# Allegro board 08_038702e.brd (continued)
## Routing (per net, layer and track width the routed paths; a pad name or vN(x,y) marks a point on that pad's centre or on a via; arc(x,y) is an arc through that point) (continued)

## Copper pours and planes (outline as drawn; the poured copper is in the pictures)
0.95V on TOP: 10.72,7.47 10.72,3.28 8.31,3.28 8.31,5.95 8.18,6.08 7.55,6.08 7.55,7.47
0.95V on BOTTOM: 10.34,7.47 10.34,2.01 7.55,2.01 7.55,7.47
0.95V on L9_POWER: 27.61,36.81 29.14,34.53 51.49,34.53 52.88,33.13 52.88,26.14 53.01,26.14 55.93,23.22 62.03,23.22 64.95,20.3 64.95,17.63 63.68,16.36 61.52,16.36 61.14,15.98 59.74,15.98 58.73,14.97 58.09,14.97 55.3,12.17 52.25,12.17 51.87,11.79 49.96,11.79 48.44,10.27 30.91,10.27 28.63,7.98 28.63,6.84 28.37,6.59 21.01,6.59 16.56,2.14 15.8,2.14 14.4,0.74 8.94,0.74 7.04,2.65 7.04,4.93 3.74,8.24 2.97,8.24 0.56,10.65 0.56,41 1.45,41.89 5.51,41.89 6.4,41 6.4,38.84 5.13,37.57 5.13,37.07 5.64,36.56 5.64,33.13 6.78,31.99 15.17,31.99 20.12,36.94 24.31,37.32 27.23,37.07 27.48,36.94 ; 1 cut-out
0.95V on L12_POWER: 6.53,0.62 6.28,1.25 6.28,5.06 4.5,6.84 1.58,6.84 0.56,7.86 0.56,51.8 1.96,53.19 6.53,53.19 8.31,51.42 8.31,34.78 5.77,32.24 5.77,18.65 6.66,17.76 16.56,17.76 18.98,15.35 31.42,15.35 34.34,12.43 37.39,12.43 41.2,8.62 53.01,8.62 53.77,9.38 53.77,11.28 52.88,12.17 51.23,12.17 50.98,12.43 50.98,13.44 51.23,13.7 56.82,13.7 57.58,14.46 57.58,16.49 61.27,20.17 63.68,20.17 63.74,20.11 81.65,20.11 83.87,17.89 83.87,1.76 82.73,0.62 16.56,0.62 15.93,1.25 15.17,1.25 14.53,0.62 ; 7 cut-outs
1.0V on TOP: 52,12.05 54.03,12.05 54.92,12.94 56.82,12.94 57.58,13.57 58.6,13.57 59.11,12.81 59.49,13.32 59.11,13.95 59.11,14.33 58.85,14.59 52.76,14.59 52,13.82
1.8V on TOP: 64.57,3.28 64.57,1.63 59.23,1.63 59.23,3.41 59.62,3.79 60.12,3.79 60.38,4.05 60.38,6.08 60.89,6.08 60.89,3.66 61.27,3.28
1.8V on L10_POWER: 58.47,12.68 58.47,2.78 58.98,2.27 62.41,2.27 65.08,4.93 67.49,4.93 68.38,4.05 68.38,1.63 68.76,1.25 78.03,1.25 80.44,3.66 80.44,6.46 78.54,8.36 75.87,8.36 75.62,8.11 75.62,6.84 75.36,6.59 72.06,6.59 70.92,7.73 70.92,10.4 69.65,11.67 66.35,11.67 63.93,14.08 59.87,14.08 ; 2 cut-outs
1.8V on L11_POWER: 13.64,13.95 15.8,13.95 15.8,5.44 16.05,5.19 19.74,5.19 23.17,8.62 67.24,8.62 67.24,9.51 71.17,9.51 71.81,10.14 71.81,12.43 72.95,13.57 83.24,13.57 84.13,12.68 84.13,1.63 83.11,0.62 18.34,0.62 13.64,5.32 ; 7 cut-outs
1.35V on TOP: 59.74,13.82 62.54,13.82 62.92,14.21 64.31,14.21 64.31,14.97 63.68,15.6 59.62,15.6 59.49,15.48 59.49,14.08
1.35V on L18_SIG: 30.15,1.63 30.15,3.41 50.22,3.41 51.11,4.3 51.11,10.52 52.88,12.3 52.88,14.84 53.14,15.09 59.74,15.09 59.87,14.97 62.16,14.97 62.54,14.59 62.54,13.95 62.28,13.7 61.39,13.7 60.76,13.06 60.76,1.89 59.87,1 34.34,1 33.83,1.51 32.06,1.51 31.55,1 30.79,1
3.3V on L11_POWER: 81.46,60.18 81.46,52.56 73.84,52.56 73.84,57 56.8,56.89 56.89,56.96 56.86,57.07 56.83,57.1 56.76,57.13 56.68,57.11 56.54,57.04 56.38,57.05 56.28,57.03 56.25,56.93 56.25,56.89 55.04,56.88 54.15,57.77 53.65,57.77 52.88,57 39.3,57 39.3,53.19 34.47,53.19 34.47,57 28.75,57 28.75,59.04 9.96,59.04 9.96,56.62 7.29,53.96 7.29,43.54 2.85,39.1 2.85,38.59 2.08,37.83 1.2,37.83 0.94,38.08 0.94,39.61 1.83,40.49 1.83,41.51 4.75,44.43 4.75,60.18 5.89,61.32 80.44,61.32 ; 2 cut-outs
GND on TOP: outline of 175 points within 57.84,33.14 97.22,55.47
GND on TOP: outline of 116 points within 59.74,7.11 97.48,24.99 ; 1 cut-out
GND on TOP: 96.57,7.35 96.57,11.92 91.75,11.92 91.75,15.6 96.57,15.6 96.57,20.81 92,20.81 92,24.62 96.57,24.62 96.57,33.51 91.87,33.51 91.87,37.32 96.57,37.32 96.57,42.4 92,42.4 92,46.21 96.57,46.21 96.57,51.16 91.75,51.16 91.75,55.23 99.62,55.23 99.62,7.35
GND on TOP: 78.03,23.86 76.77,24.38 76.25,25.64 76.25,26.4 76.77,27.65 78.03,28.18 78.88,28.18 79.46,28.39 80.08,28.47 80.82,28.47 81.55,28.85 82.36,28.98 93.21,28.98 93.77,29.31 94.4,29.43 95.45,29.43 96.7,28.91 97.22,27.65 97.22,26.66 96.7,25.41 95.45,24.89 94.4,24.89 93.98,24.94 93.58,25.09 82.82,25.09 82.01,24.71 81.14,24.58 81.11,24.58 80.48,24.05 79.68,23.86
GND on TOP: 15.04,3.28 15.04,0.62 17.71,0.62 18.21,1.12 18.21,2.9 19.61,4.3 21.77,4.3 21.77,4.81 21.26,4.81 21.26,7.22 20.12,7.22 18.85,5.95 18.85,5.19 17.71,4.05 15.67,4.05 15.17,3.41
GND on BOTTOM: 11.61,0.36 11.61,6.84 13.01,6.84 13.01,4.81 14.78,4.81 14.78,2.01 18.34,2.01 18.34,0.36
GND on BOTTOM: 22.53,7.22 22.53,5.19 24.31,5.19 24.31,7.22
GND on BOTTOM: 60.38,34.53 60.38,24.62 70.16,24.62 70.16,34.53 ; 1 cut-out
GND on L2_GND: 3.74,0.62 2.34,1 1.2,2.01 0.69,3.16 0.69,58.27 0.94,59.54 1.58,60.43 2.59,61.2 3.74,61.32 96.7,61.32 97.59,61.2 98.6,60.43 99.11,59.67 99.37,58.66 99.37,3.41 99.11,2.39 98.6,1.51 97.59,0.87 96.45,0.62 ; 12 cut-outs
GND on L3_SIG: 99.37,54.85 99.37,7.6 86.29,7.6 82.22,11.67 66.47,11.67 66.47,14.59 65.2,15.73 63.3,15.73 62.16,16.87 62.16,17.51 61.01,17.89 61.01,21.44 65.58,21.44 65.58,19.29 66.6,18.27 69.01,18.27 70.41,19.67 73.84,19.67 76.76,22.59 76.76,40.88 76.13,41.51 73.33,41.51 72.06,40.24 72.06,38.72 70.66,38.72 68.76,40.62 59.36,40.62 59.36,42.02 62.16,43.42 66.35,47.61 75.49,47.61 77.78,49.89 77.78,52.43 80.19,54.85 ; 1 cut-out
GND on L5_GND: 3.74,0.62 2.21,1 1.07,2.14 0.69,3.28 0.69,58.91 1.32,60.31 2.34,61.2 3.74,61.32 96.57,61.32 97.59,61.2 98.6,60.43 99.11,59.67 99.37,58.53 99.37,3.41 99.11,2.39 98.6,1.51 97.59,0.87 96.45,0.62 ; 6 cut-outs
GND on L8_GND: 3.74,0.62 2.21,1 1.07,2.14 0.69,3.28 0.69,58.91 1.32,60.31 2.34,61.2 3.74,61.32 96.57,61.32 97.59,61.2 98.6,60.43 99.11,59.67 99.37,58.53 99.37,3.41 99.11,2.39 98.6,1.51 97.59,0.87 96.45,0.62 ; 6 cut-outs
GND on L13_GND: 3.74,0.62 2.21,1 1.07,2.14 0.69,3.28 0.69,58.91 1.32,60.31 2.34,61.2 3.74,61.32 96.57,61.32 97.59,61.2 98.6,60.43 99.11,59.67 99.37,58.53 99.37,3.41 99.11,2.39 98.6,1.51 97.59,0.87 96.45,0.62 ; 6 cut-outs
GND on L16_GND: 3.74,0.62 2.21,1 1.07,2.14 0.69,3.28 0.69,58.91 1.32,60.31 2.34,61.2 3.74,61.32 96.57,61.32 97.59,61.2 98.6,60.43 99.11,59.67 99.37,58.53 99.37,3.41 99.11,2.39 98.6,1.51 97.59,0.87 96.45,0.62 ; 6 cut-outs
GND on L19_GND: 3.74,0.62 2.21,1 1.07,2.14 0.69,3.28 0.69,58.91 1.32,60.31 2.34,61.2 3.74,61.32 96.57,61.32 97.59,61.2 98.6,60.43 99.11,59.67 99.37,58.53 99.37,3.41 99.11,2.39 98.6,1.51 97.59,0.87 96.45,0.62 ; 8 cut-outs
VCC-1P35 on BOTTOM: 47.55,61.58 47.55,60.18 48.57,60.18 48.57,61.58
VCC-1P35 on L12_POWER: 48.95,14.59 56.82,14.59 56.82,16.62 59.23,19.03 59.23,58.02 55.81,61.45 47.55,61.45 45.39,59.29 38.66,59.29 38.15,58.78 38.15,57.77 38.66,57.26 42.09,57.26 44.63,54.72 48.19,54.72 48.95,53.96 ; 1 cut-out
VCC-3P3V on BOTTOM: 42.98,59.93 42.98,61.45 44.88,61.45 45.39,60.69 46.15,60.69 46.15,60.18 45.14,60.18 44.88,59.93
VCC-3P3V on L3_SIG: 10.34,54.21 10.34,59.93 10.85,60.43 22.91,60.43 22.91,58.53 15.04,58.53 15.04,54.21
VCC-3P3V on L6_SIG: 21.39,58.66 21.39,61.45 46.03,61.45 46.03,59.8 23.42,59.8 23.42,58.66
VCC-3P3V-IO on L11_POWER: 5.01,31.1 26.6,31.1 26.6,37.83 31.93,37.83 31.93,27.41 30.91,26.4 16.18,26.4 15.8,26.02 11.74,26.02 11.61,25.89 11.61,11.16 7.61,7.16 5.2,7.16 5.13,7.22 2.97,7.22 2.34,7.86 2.34,11.41 6.02,11.41 6.78,12.17 6.78,13.19 6.4,13.57 4.5,13.57 3.1,14.97 3.1,17.63 5.01,19.54
VCC-3P3V-IO on L12_POWER: 38.28,12.17 38.28,12.94 34.72,12.94 28.25,19.41 28.25,24.87 26.34,26.78 26.34,32.87 27.87,34.4 27.87,37.19 33.58,37.19 33.58,41.64 33.33,41.89 11.86,41.89 11.23,42.53 11.23,54.85 26.47,54.85 26.47,59.67 31.93,59.67 31.93,54.85 33.71,54.85 33.71,50.65 46.03,50.65 46.03,47.73 31.42,47.73 31.42,52.69 14.78,52.69 13.26,51.16 13.26,49.13 14.59,47.8 19.17,47.8 23.55,43.42 35.74,43.42 35.74,34.27 29.52,28.05 29.52,26.14 30.15,25.51 30.15,20.81 35.61,15.35 38.53,15.35 39.68,14.21 40.44,14.21 42.6,12.05 42.6,9.13 41.33,9.13 ; 1 cut-out
VCCO-DDR on TOP: 48.95,2.9 48.95,6.59 53.39,6.59 53.39,5.19 50.09,5.19 50.09,2.9
VCCO-DDR on BOTTOM: 48.69,4.93 48.69,2.27 49.71,2.27 49.71,4.93
VCCO-DDR on L10_POWER: 52.25,15.73 50.09,15.73 48.44,14.08 48.44,5.95 49.2,5.19 49.2,3.54 49.46,3.28 52.76,3.28 53.01,3.54 53.01,5.06 51.11,6.97 51.11,12.55 52.63,14.08 52.63,15.35
VCCO-DDR on L11_POWER: 25.07,14.46 22.53,14.46 18.34,18.65 18.34,24.62 40.69,24.62 40.69,18.27 45.39,13.57 50.22,13.57 50.22,16.36 52.76,16.36 52.76,10.27 29.26,10.27
VCCO_1P8V on L12_POWER: 38.03,26.52 38.03,42.91 37.01,43.92 26.98,43.92 25.83,45.07 22.4,45.07 19.1,48.37 14.66,48.37 13.64,49.38 13.64,50.02 14.78,51.16 20.75,51.16 22.91,49 27.36,49 29.52,46.84 47.04,46.84 48.31,45.57 48.31,34.4 48.44,34.4 48.44,26.52
VCCO_12 on TOP: 14.15,37.57 14.15,36.43 15.17,36.43 15.17,37.57
VCCO_12 on L9_POWER: 18.85,15.73 18.85,30.72 21.13,30.72 21.13,34.02 23.29,34.4 23.93,34.78 24.44,34.78 26.34,34.02 26.34,32.37 24.94,30.97 24.94,28.94 26.47,27.41 26.47,26.4 23.55,23.48 23.55,17.13 26.72,17.13 26.72,16.11 26.34,15.73
VCCO_12 on L11_POWER: 13.26,32.87 13.26,37.83 17.83,37.83 17.83,36.3 25.45,36.3 25.71,36.05 25.71,31.73 25.45,31.48 18.21,31.48 16.82,32.87
VCCO_13 on TOP: 17.2,38.34 17.2,36.94 18.34,36.94 19.1,36.18 19.1,31.73 18.34,30.97 18.34,17 19.36,15.98 21.39,15.98 21.77,16.36 21.77,16.62 21.52,16.87 19.48,16.87 19.1,17.25 19.1,24.75 20.12,25.76 20.12,26.27 19.1,27.29 19.1,30.21 20.12,31.22 20.12,35.8 19.99,35.92 19.99,36.94 18.59,38.34
VCCO_13 on L12_POWER: 18.09,16.62 18.09,18.27 6.91,18.27 6.21,18.97 6.21,22.65 12.75,29.19 12.75,37.19 13.39,37.83 15.42,37.83 15.67,37.57 15.67,36.56 16.82,35.41 21.01,35.41 22.02,34.4 22.02,25.38 27.1,25.38 27.61,24.87 27.61,17 26.47,15.86 18.85,15.86
VCCO_33_34 on TOP: 19.61,41.89 19.61,40.49 17.07,40.49 17.07,41.89
VCCO_33_34 on L11_POWER: 40.95,18.65 40.95,29.83 38.41,29.83 38.15,30.08 38.15,31.99 32.56,31.99 32.56,38.34 18.98,38.34 17.32,39.99 17.32,42.27 15.04,44.56 15.04,46.72 46.92,46.72 47.42,46.21 47.42,44.81 48.19,44.05 48.19,35.67 52.12,31.73 56.82,31.73 56.82,28.05 49.84,28.05 49.84,23.73 47.68,21.57 44.76,21.57 44.25,21.06 44.25,19.92 45.01,19.16 49.2,19.16 49.84,18.52 49.84,14.08 45.52,14.08
VCCPCOM-1P8V on L10_POWER: 6.66,1.76 6.66,13.82 1.07,13.82 1.07,29.95 15.17,29.95 15.24,37.51 15.29,37.56 15.33,37.59 15.36,37.64 15.33,37.68 15.32,37.69 15.28,37.7 15.24,37.7 15.17,42.53 15.29,42.65 15.29,43.03 15.17,43.29 11.99,46.46 5.39,46.46 5.39,51.92 10.59,51.92 14.66,55.99 14.66,60.18 48.31,60.18 49.46,61.32 53.14,61.32 54.28,60.18 67.36,60.18 69.52,58.02 69.52,50.15 65.46,46.08 61.39,46.08 60.38,47.1 60.38,49.77 58.6,51.54 32.06,51.54 30.91,50.4 30.91,46.34 33.07,44.18 33.07,37.19 36.88,37.19 36.88,32.87 33.07,32.87 33.07,27.41 50.09,27.41 51.87,25.64 51.87,24.87 48.06,21.06 48.06,15.6 47.93,15.6 47.93,5.82 48.82,4.93 48.82,2.9 47.93,2.01 40.69,2.01 40.69,15.6 31.17,15.6 31.17,18.4 22.91,18.4 22.91,13.82 15.42,13.82 14.53,12.94 14.53,10.65 15.93,9.25 15.93,1.76 ; 5 cut-outs
VCCPINT on L2_GND: 51.11,11.16 51.11,10.01 51.87,9.25 53.39,9.25 53.39,11.16
VCCPINT on L10_POWER: 51.74,10.4 53.01,10.4 53.52,9.89 53.52,9.51 54.03,9 54.03,8.11 57.84,4.3 57.84,2.01 58.09,1.76 62.79,1.76 65.58,4.55 67.24,4.55 67.74,4.05 67.74,1.63 66.73,0.62 56.69,0.62 55.68,1.63 55.68,4.05 53.27,6.46 53.27,8.49 52.88,8.87 51.87,8.87 51.49,9.25 51.49,10.14
VCCPINT on L12_POWER: 45.9,9.13 44.76,10.27 44.25,10.27 43.87,10.65 43.87,12.43 41.33,14.97 39.55,14.97 38.79,15.73 36.25,15.73 34.72,17.25 34.72,24.49 30.53,24.49 30.53,25.76 29.9,26.4 29.9,26.91 30.53,27.54 37.52,27.54 37.52,26.4 37.77,26.14 37.77,20.17 40.69,17.25 48.44,17.25 48.44,14.21 48.82,13.82 48.82,11.67 52.5,11.67 53.39,10.78 53.39,9.76 52.76,9.13
VDD_INTERFACE on L10_POWER: 61.9,18.65 64.44,16.11 70.28,16.11 72.32,14.08 75.11,14.08 75.11,6.97 73.71,6.97 72.19,8.49 72.19,10.78 70.92,12.05 69.78,12.05 68.38,13.44 65.08,13.44 63.93,14.59 61.52,14.59 60,16.11 60,22.21 58.98,23.22 58.09,23.22 56.44,24.87 56.44,32.49 59.87,32.49 60.89,31.48 60.89,30.72 59.62,29.45 59.62,25.76 60,25.38 61.77,25.38 62.28,24.87 62.28,23.6 61.9,23.22 ; 2 cut-outs
VDDA_GPO_PWR on L10_POWER: 86.54,46.46 86.54,57.26 80.7,57.26 80.7,60.18 88.32,60.18 88.32,46.46
VIN on TOP: 16.94,42.78 16.94,44.43 17.58,44.43 17.58,44.69 18.34,44.69 18.34,45.96 19.61,45.96 19.61,42.78
VIN on TOP: 19.1,0.62 18.98,0.74 18.98,3.41 21.13,3.41 21.77,2.78 23.17,2.78 23.17,3.66 23.04,3.92 23.04,4.68 23.17,4.81 24.31,4.81 24.56,5.06 24.56,5.32 25.33,5.32 25.45,5.19 25.45,2.78 25.96,2.39 25.96,0.62
VIN on L9_POWER: 29.52,8.24 31.04,9.76 48.69,9.76 50.09,11.16 52.76,11.16 53.52,11.92 55.81,11.92 58.6,14.71 58.98,14.71 59.87,15.6 61.27,15.6 61.65,15.98 63.93,15.98 67.74,19.79 70.92,19.79 74.73,23.6 74.73,43.67 73.46,44.94 52.25,44.94 51.49,45.7 20.12,45.7 19.61,45.19 19.61,43.42 18.09,41.89 16.82,41.89 16.05,42.65 16.05,47.99 25.71,57.64 43.36,57.64 44.5,56.5 48.19,56.5 49.33,57.64 58.85,57.64 59.49,57 59.49,48.5 59.74,48.24 77.14,48.24 79.3,46.08 79.3,13.7 77.4,11.79 68.38,11.79 64.7,8.11 64.7,1.63 29.14,1.63 27.99,0.62 18.21,0.62 18.09,0.74 18.09,2.9 21.01,5.82 21.39,5.82 21.52,5.7 21.52,5.19 21.64,5.06 23.93,5.06 24.06,5.19 24.06,5.7 24.18,5.82 27.1,5.82 27.48,6.2 28.5,6.2 29.52,7.22 ; 4 cut-outs
1P3_SUPPLY_A on L11_POWER: 63.68,9 63.68,19.54 66.47,19.54 69.78,22.84 69.78,23.35 69.01,24.11 69.01,25.51 70.16,26.65 70.16,27.29 70.41,27.54 74.35,27.54 74.86,28.05 74.86,29.7 74.47,30.08 70.66,30.08 70.16,30.59 70.16,31.35 70.54,31.73 74.09,31.73 74.86,32.49 74.86,33.64 74.09,34.4 70.92,34.4 70.54,34.78 70.54,36.81 74.73,36.81 78.03,33.51 78.03,21.95 70.92,14.84 70.92,11.92 71.17,11.92 71.17,10.52 71.05,10.4 66.73,10.4 66.6,10.27 66.6,9 ; 2 cut-outs
1P3_SUPPLY_B on BOTTOM: 66.47,40.37 66.47,39.73 65.58,38.84 64.82,38.84 64.7,38.72 64.7,37.57 64.82,37.45 65.58,37.45 65.84,37.7 68.63,37.7 68.89,37.95 68.89,38.72 68.51,39.1 68.51,39.99 67.87,40.62 66.73,40.62
1P3_SUPPLY_B on L10_POWER: 75.62,8.74 75.62,14.84 72.44,14.84 72.44,14.97 70.92,16.49 64.82,16.49 62.28,19.03 62.28,22.08 68.89,22.08 70.66,23.86 70.66,25.89 70.92,26.14 74.86,26.14 75.36,26.65 75.36,29.45 74.73,30.08 72.95,30.08 72.7,30.33 72.7,34.91 70.28,37.32 64.7,37.32 64.31,36.94 64.31,34.53 64.06,34.27 61.39,34.27 59.62,36.05 59.62,43.42 60.12,43.92 70.92,43.92 74.35,40.49 74.35,36.3 76.76,33.89 80.19,33.89 80.19,14.84 79.68,14.84 79.68,10.14 77.4,10.14 77.4,8.74 ; 1 cut-out
1P3_SUPPLY_B on L19_GND: 64.7,38.72 64.7,37.45 66.22,37.45 66.22,38.72
JX_MGTAVCC on TOP: 8.18,37.45 8.18,34.14 5.89,34.14 5.89,36.18 7.16,37.45
JX_MGTAVCC on L11_POWER: 4.24,13.19 5.89,13.19 6.15,12.94 6.15,12.3 5.77,11.92 1.2,11.92 0.81,12.3 0.81,33 3.74,35.92 6.91,35.92 7.29,35.54 7.29,34.91 2.59,30.21 2.59,14.84
JX_MGTAVTT on TOP: 10.85,37.7 10.85,35.29 11.86,35.29 11.86,37.7
JX_MGTAVTT on L4_SIG: 10.59,37.7 10.59,36.3 10.85,36.05 11.23,36.05 11.36,36.18 11.36,37.45 10.97,37.83 10.72,37.83
JX_VCCO_12 on TOP: 12.63,37.57 12.63,34.53 13.77,34.53 13.77,37.57
JX_VCCO_12 on L9_POWER: 16.82,60.31 63.17,60.31 64.82,58.66 64.7,50.4 63.17,48.88 60.63,48.88 60,49.51 60,58.15 49.2,58.15 48.19,57.13 44.63,57.13 43.61,58.15 25.33,58.15 13.77,46.59 13.77,37.83 14.66,36.94 14.66,34.91 14.4,34.65 12.75,34.65 11.23,36.18 11.23,54.72
JX_VCCO_13 on TOP: 15.8,38.34 15.8,35.16 16.94,35.16 16.94,38.34
JX_VCCO_33_34 on TOP: 14.66,39.35 14.66,40.11 16.05,40.11 16.05,41.26 16.82,41.26 16.82,39.35
JX_VCCO_33_34 on L14_SIG: 14.91,40.37 14.91,39.35 16.94,39.35 16.94,40.37
JX_VCCO_33_34 on L14_SIG: 11.36,0.49 11.23,0.62 11.23,13.95 4.24,13.95 1.07,17.13 1.07,35.41 2.47,36.81 14.91,36.81 15.42,37.32 15.42,38.34 14.28,39.48 14.28,40.37 16.94,40.37 16.94,33.13 13.26,33.13 10.59,30.46 6.28,30.46 3.35,27.54 3.35,22.71 2.34,21.7 2.34,17.76 8.94,17.76 13.01,13.7 13.01,11.28 13.39,9.51 13.39,9 20.37,2.01 58.85,2.01 61.27,4.43 61.27,7.22 63.04,7.22 63.04,0.62 62.92,0.49 ; 1 cut-out
JX_VIN on TOP: 16.56,44.18 16.56,41 14.66,41 14.66,44.18
JX_VIN on BOTTOM: 53.27,11.92 53.27,4.55 54.54,4.55 54.54,11.92
JX_VIN on BOTTOM: 53.39,57 53.39,49 54.54,49 54.54,52.31 55.04,52.81 55.04,53.7 54.54,54.21 54.54,57
JX_VIN on L10_POWER: 53.77,17.89 53.77,9.63 54.28,9.13 55.93,9.13 57.08,10.27 57.08,18.78 59.62,21.32 59.62,22.08 59.11,22.59 58.47,22.59
JX_VIN on L11_POWER: 57.84,21.44 57.84,38.72 62.03,38.72 62.03,50.02 55.3,50.02 55.3,49.77 54.54,49 53.52,49 52.38,50.15 48.69,50.15 45.65,47.1 14.91,47.1 14.53,46.72 14.53,44.56 16.56,42.53 16.56,39.22 15.8,38.46 11.99,38.46 11.48,38.97 11.48,52.05 14.02,54.59 31.93,54.59 33.96,52.56 39.55,52.56 43.36,56.37 52.63,56.37 53.65,57.39 53.9,57.39 54.79,56.5 66.09,56.5 66.09,50.02 65.97,50.02 65.97,34.65 60,34.65 60,21.44 ; 2 cut-outs
JX_VIN on L17_SIG: 34.85,3.92 34.85,4.17 35.23,4.55 35.61,4.55 35.8,4.36 40.88,4.36 41.45,3.79 51.74,3.79 53.14,5.19 54.41,5.19 54.66,4.93 54.66,2.9 53.77,2.01 41.2,2.01 39.93,3.28 35.49,3.28 ; 1 cut-out
MGTAVCC on L12_POWER: 8.94,34.91 12.12,34.91 12.12,37.32 13.01,38.21 15.8,38.21 16.18,37.83 16.18,36.68 16.94,35.92 21.13,35.92 22.15,34.91 27.23,34.91 27.23,37.45 27.87,38.08 32.82,38.08 32.82,41.38 8.94,41.38 ; 1 cut-out
MGTAVTT on L9_POWER: 10.34,35.29 11.23,35.29 12.37,34.14 14.78,34.14 15.04,34.4 15.04,35.03 18.47,38.46 18.47,41.51 19.99,43.03 19.99,44.94 20.37,45.32 23.93,45.32 25.33,43.92 31.55,43.92 31.55,37.32 25.45,37.32 24.69,37.57 23.67,37.57 19.99,37.32 19.48,36.81 16.56,34.02 15.42,32.87 11.99,32.87 10.09,35.03 ; 1 cut-out
PG_1P8V on L17_SIG: 37.39,2.78 39.68,2.78 40.82,1.63 66.22,1.63 66.73,2.14 66.73,4.68 67.74,5.7 71.43,5.7 71.43,2.65 71.55,2.65 72.7,1.51 77.9,1.51 79.05,2.65 79.05,6.71 80.57,6.71 80.57,1.63 79.55,0.62 37.39,0.62 37.01,1 37.01,2.39
PHY1_1V8 on L15_SIG: 10.09,1.76 10.09,11.03 11.99,12.94 11.99,13.7 14.53,16.24 14.53,18.4 16.69,18.4 16.69,12.94 13.9,12.94 13.26,12.3 13.26,10.52 13.77,10.01 13.77,7.73 13.26,7.22 12.5,7.22 11.99,6.71 11.99,6.08 12.5,5.57 14.4,5.57 17.32,8.49 25.83,8.49 26.47,9.13 27.61,9.13 31.04,5.7 31.04,1.76
PHY1_AVDD_1V8 on L12_POWER: 13.13,8.36 13.13,10.65 14.85,12.36 23.1,12.36 24.56,10.9 24.56,5.06 24.31,4.81 16.69,4.81 ; 1 cut-out
PHY1_AVDD_3V3 on L11_POWER: 14.28,19.03 14.28,14.33 16.18,14.33 16.18,5.82 16.44,5.57 19.61,5.57 19.86,5.82 19.86,11.16 20.5,11.79 24.82,11.79 25.71,12.68 25.71,13.44 25.07,14.08 20.37,14.08 19.86,14.59 19.86,15.35 18.47,15.35 18.47,19.03
PHY1_VDD_3V3 on L10_POWER: 15.93,13.32 14.91,12.3 14.91,11.03 16.94,9 28.37,9 29.39,10.01 29.39,11.67 27.74,13.32
SW2 on L2_GND: 62.16,8.87 62.16,9.76 63.3,9.76 63.68,10.14 63.68,11.03 63.3,11.41 62.16,11.41 61.65,11.92 61.65,12.17 61.52,12.55 61.65,13.19 62.03,13.19 63.04,12.17 64.44,12.17 64.44,9.76 63.55,8.87
UNNAMED_9_ADP238X_I1088_SW1 on TOP: 16.94,4.68 16.94,7.86 18.34,9.25 22.28,9.25 22.28,8.11 21.26,8.11 21.26,7.6 19.99,7.6 19.99,7.47 19.74,7.22 19.23,7.22 18.47,6.46 18.47,5.44 17.71,4.68
UNNAMED_9_ADP238X_I1088_SW1 on L2_GND: 21.39,7.86 21.39,5.06 22.66,5.06 22.66,7.86
UNNAMED_9_ADP238X_I1088_SW1 on L3_SIG: 20.75,9.25 20.75,3.03 22.66,3.03 22.66,9.25
UNNAMED_9_ADP238X_I1088_SW1 on L4_SIG, L6_SIG, L7_SIG: 20.75,9 20.75,4.05 22.79,4.05 22.79,9
UNNAMED_9_ADP238X_I1088_SW1 on L10_POWER: 20.25,8.36 20.25,4.17 22.53,4.17 22.53,8.36
UNNAMED_9_CAP_I1113_N1 on TOP: 11.36,4.17 12.12,4.93 12.12,7.35 15.42,7.35 15.42,4.68 14.4,3.66 14.4,2.39 11.61,2.39 11.36,2.65
VTT_0P75 on TOP: 49.2,61.07 51.23,61.07 52.12,60.18 52.12,58.27 52.38,58.02 52.38,55.1 53.27,54.21 53.27,51.8 56.69,48.37 56.69,47.35 49.84,47.35 49.71,47.23 49.71,46.84 49.2,46.84
VTT_0P75 on BOTTOM: 48.31,59.29 48.82,59.04 51.87,59.04 51.87,60.18 49.33,60.18 48.31,59.42
VTT_0P75 on L11_POWER: 47.8,45.07 47.8,48.5 48.95,49.64 51.87,49.64 52.88,48.62 59.11,48.62 60.12,49.64 61.14,49.64 61.14,40.37 59.87,39.1 49.33,39.1 48.57,39.86 48.57,44.3

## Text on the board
BOTTOM: Z7PZ-SDR2-PCB-E
User.Comments: SECONDARY SIDE | ASSEMBLY | 3 | 1 | SOLDER BLOB TO CONNECT PINS 1 & 2 OF JP1 THRU JP4
Ref Des/Silkscreen Top: SDS | SDC | PGOOD | CFG DONE | JTAG  S4 0 S3 0 | QSPI  S4 1 S3 0 | SD   S4 1 S3 1 | 0 | 1 | BD-Z7PZ-SDR2-G
PAGE_OUTLINE: B | C | D | E | ENGINEERING CHANGES | 06MAR15 | 25JUN15 | 23OCT15 | 13JAN16 | 27SEP16 | C.E. | EVAL BOARD | 02-038702
DIMENSION: 15.    INDICATED VIAS TO BE NON-CONDUCTIVE EPOXY FILLED, AND GROUND FLUSH PRIOR | TO OVER PLATING. | SEE NOTE 15 | 4 PLACES
User.8: LAYER 2 GND | 08-      -07
User.9: LAYER 3 SIGNAL | 08-      -08
User.10: 16.    BOARDS TO BE PANELIZED AND SHIPPED INTACT. | IMMERSION GOLD OVER 100-200 MICROINCHES OF ELECTROLESS NICKEL. | 14.    FINISH: SURFACES SHALL HAVE ENIG FINISH PLATED WITH 2-6 MICROINCHES OF
User.11: LAYER 4 SIGNAL | 08-      -09
User.12: LAYER 5 GND | 08-      -10
User.14: LAYER 6 SIGNAL | 08-      -11
User.15: LAYER 7 SIGNAL | 08-      -12
User.16: LAYER 8 GND | 08-      -13
User.17: LAYER 9 POWER | 08-      -14
User.18: INTERNAL SIGNAL (LAYER 14) | INTERNAL SIGNAL (LAYER 15) | GROUND PLANE    (LAYER 16) | INTERNAL SIGNAL (LAYER 17) | INTERNAL SIGNAL (LAYER 18) | GROUND PLANE    (LAYER 19)
User.24: LAYER 10 POWER | 08-      -15
User.25: LAYER 11 POWER | 08-      -16
User.26: LAYER 12 POWER | 08-      -17
User.27: LAYER 13 GROUND | 08-      -18
User.28: LAYER 14 SIGNAL | 08-      -19
User.29: LAYER 15 SIGNAL | 08-      -20
User.30: LAYER 16 GND | 08-      -21
User.31: LAYER 17 SIGNAL | 08-      -22
User.32: LAYER 18 SIGNAL | 08-      -23
User.33: LAYER 19 GND | 08-      -24
User.34: LAYER 20 GND | 08-      -25
User.35: LAYER 21 SIG | 08-      -26
User.36: LAYER 22 SIG | 08-      -27
User.37: LAYER 23 GND | 08-      -28
User.39: SECONDARY SIDE
User.45: 3 | 4 | 2 | FIGURE | SIZE | 5.0 | 6.0 | 8.0 | 10.0 | 31.0 | 47.0 | 155.0 | PLATED | NON-PLATED | FINISHED HOLES IN MILS | ALL UNITS ARE IN MILS | DRILLED HOLES LAYER 1 TO LAYER 2 | DRILLED HOLES LAYER 19 TO LAYER 20 | DRILLED HOLES LAYER 2 TO LAYER 19 | QTY | 125 | 168 | 239 | 944 | 1845 | 158 | SEE NOTE 15 | TOLERANCE/NOTES
